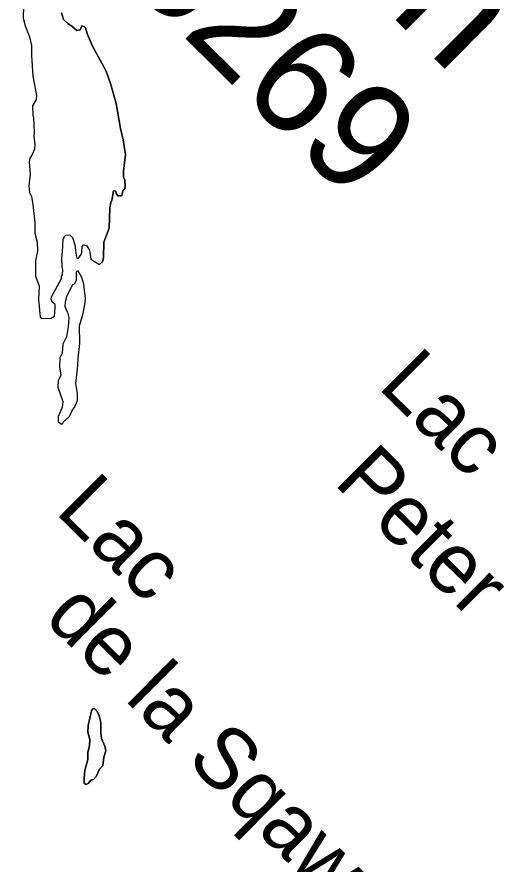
# Model space of a CAD drawing. Extents: x 642515 to 647219, y 6080136 to 6084356.
# Drawn here: x 645090.28 to 645112.82, y 6080946.67 to 6080985.89 of the extents above; entities that cross this region are included whole.
import ezdxf

# ---------------------------------------------------------------- set-up
doc = ezdxf.new("R2010")
doc.units = 0
doc.layers.add('Level 63', color=7, linetype='Continuous')

msp = doc.modelspace()

# ---------------------------------------------------------------- linework, layer by layer
at = {"layer": 'Level 63'}
for points in [[(645090.58, 6080986.39), (645090.56, 6080985.84), (645090.65, 6080985.48), (645090.85, 6080984.97), (645090.95, 6080984.57), (645090.95, 6080984.09), (645091.01, 6080983.16), (645091.18, 6080982.25), (645091.16, 6080982.07), (645090.99, 6080981.78), (645091.01, 6080981.35), (645091.04, 6080981.24), (645091.07, 6080980.56), (645091.05, 6080980.35), (645091.11, 6080979.99), (645091.09, 6080979.78), (645090.98, 6080979.52), (645090.87, 6080979.36), (645090.84, 6080979.19), (645090.89, 6080978.61), (645090.83, 6080978.07), (645090.85, 6080977.77), (645090.95, 6080977.58), (645091.01, 6080977.21), (645091.1, 6080976.38), (645091.1, 6080975.89), (645091.21, 6080975.47), (645091.22, 6080975.06), (645091.13, 6080974.6), (645091.14, 6080973.9), (645091.3, 6080973.44), (645091.27, 6080972.81), (645091.35, 6080971.99), (645091.44, 6080971.93), (645091.86, 6080971.95), (645092.01, 6080972.04), (645092.05, 6080972.41), (645092.04, 6080972.58), (645091.91, 6080972.69), (645091.86, 6080972.82), (645091.88, 6080972.93), (645092.34, 6080973.78), (645092.34, 6080973.86), (645092.38, 6080973.97), (645092.4, 6080974.2), (645092.36, 6080974.33), (645092.35, 6080974.71), (645092.39, 6080975.04), (645092.41, 6080975.59), (645092.47, 6080975.73), (645092.54, 6080975.79), (645092.72, 6080975.81), (645092.85, 6080975.68), (645092.96, 6080975.34), (645093.01, 6080974.85), (645093.04, 6080974.73), (645093.12, 6080974.73), (645093.24, 6080974.9), (645093.28, 6080974.99), (645093.3, 6080975.26), (645093.36, 6080975.34), (645093.5, 6080975.31), (645093.64, 6080975.1), (645093.69, 6080974.68), (645094.09, 6080974.44)], [(645090.58, 6080986.39), (645090.56, 6080985.84), (645090.65, 6080985.48), (645090.85, 6080984.97), (645090.95, 6080984.57), (645090.95, 6080984.09), (645091.01, 6080983.16), (645091.18, 6080982.25), (645091.16, 6080982.07), (645090.99, 6080981.78), (645091.01, 6080981.35), (645091.04, 6080981.24), (645091.07, 6080980.56), (645091.05, 6080980.35), (645091.11, 6080979.99), (645091.09, 6080979.78), (645090.98, 6080979.52), (645090.87, 6080979.36), (645090.84, 6080979.19), (645090.89, 6080978.61), (645090.83, 6080978.07), (645090.85, 6080977.77), (645090.95, 6080977.58), (645091.01, 6080977.21), (645091.1, 6080976.38), (645091.1, 6080975.89), (645091.21, 6080975.47), (645091.22, 6080975.06), (645091.13, 6080974.6), (645091.14, 6080973.9)], [(645092.33, 6080986.09), (645092.43, 6080985.77), (645092.64, 6080985.57), (645092.82, 6080985.47), (645093.05, 6080985.27), (645093.2, 6080985.3), (645093.28, 6080985.48), (645093.38, 6080985.46), (645093.44, 6080985.39), (645093.54, 6080985.08), (645093.77, 6080984.54), (645094.41, 6080983.38), (645094.61, 6080982.81), (645094.87, 6080981.89), (645095.07, 6080980.73), (645095.19, 6080980.2), (645095.3, 6080979.53), (645095.2, 6080978.76)], [(645094.09, 6080974.44), (645094.24, 6080974.55), (645094.28, 6080974.75), (645094.3, 6080975.47), (645094.54, 6080976.12), (645094.58, 6080977.06), (645094.62, 6080977.31), (645094.67, 6080977.39), (645094.75, 6080977.84), (645094.85, 6080977.83), (645094.87, 6080977.72), (645094.95, 6080977.61), (645095.13, 6080977.61), (645095.18, 6080977.84), (645095.26, 6080977.94), (645095.28, 6080978.04), (645095.27, 6080978.34), (645095.21, 6080978.48), (645095.2, 6080978.76), (645095.3, 6080979.53), (645095.19, 6080980.2), (645095.07, 6080980.73), (645094.87, 6080981.89), (645094.61, 6080982.81), (645094.41, 6080983.38), (645093.77, 6080984.54), (645093.54, 6080985.08), (645093.44, 6080985.39), (645093.38, 6080985.46), (645093.28, 6080985.48), (645093.2, 6080985.3), (645093.05, 6080985.27), (645092.82, 6080985.47), (645092.64, 6080985.57), (645092.43, 6080985.77), (645092.33, 6080986.09)], [(645095.2, 6080978.76), (645095.21, 6080978.48), (645095.27, 6080978.34), (645095.28, 6080978.04), (645095.26, 6080977.94), (645095.18, 6080977.84), (645095.13, 6080977.61)], [(645095.13, 6080977.61), (645094.95, 6080977.61), (645094.87, 6080977.72), (645094.85, 6080977.83), (645094.75, 6080977.84), (645094.67, 6080977.39), (645094.62, 6080977.31), (645094.58, 6080977.06), (645094.54, 6080976.12), (645094.3, 6080975.47), (645094.28, 6080974.75), (645094.24, 6080974.55), (645094.09, 6080974.44)], [(645091.14, 6080973.9), (645091.3, 6080973.44), (645091.27, 6080972.81), (645091.35, 6080971.99), (645091.44, 6080971.93), (645091.86, 6080971.95), (645092.01, 6080972.04), (645092.05, 6080972.41), (645092.04, 6080972.58), (645091.91, 6080972.69), (645091.86, 6080972.82), (645091.88, 6080972.93), (645092.34, 6080973.78), (645092.34, 6080973.86), (645092.38, 6080973.97), (645092.4, 6080974.2), (645092.36, 6080974.33), (645092.35, 6080974.71), (645092.39, 6080975.04), (645092.41, 6080975.59), (645092.47, 6080975.73), (645092.54, 6080975.79), (645092.72, 6080975.81), (645092.85, 6080975.68), (645092.96, 6080975.34), (645093.01, 6080974.85), (645093.04, 6080974.73), (645093.12, 6080974.73), (645093.24, 6080974.9), (645093.28, 6080974.99), (645093.3, 6080975.26), (645093.36, 6080975.34), (645093.5, 6080975.31), (645093.64, 6080975.1), (645093.69, 6080974.68), (645094.09, 6080974.44)], [(645093.11, 6080974.14), (645093.01, 6080974.07), (645093.02, 6080973.69), (645092.93, 6080973.52), (645092.84, 6080973.49), (645092.78, 6080973.39), (645092.56, 6080972.91), (645092.5, 6080972.67), (645092.49, 6080972.51), (645092.55, 6080972.33), (645092.62, 6080972.23), (645092.67, 6080971.98), (645092.65, 6080971.55), (645092.57, 6080971.08), (645092.4, 6080970.74), (645092.37, 6080970.32), (645092.26, 6080970.11), (645092.24, 6080969.7), (645092.31, 6080969.31), (645092.18, 6080969.04), (645092.17, 6080968.76), (645092.4, 6080968.09), (645092.37, 6080967.81), (645092.18, 6080967.4), (645092.19, 6080967.16), (645092.31, 6080967.06), (645092.39, 6080967.06), (645092.42, 6080967.14), (645092.7, 6080967.4), (645092.85, 6080967.71), (645092.94, 6080967.81), (645093.08, 6080968.13), (645093.07, 6080968.46), (645093, 6080968.93), (645093.1, 6080969.74), (645093.11, 6080970.09), (645093.19, 6080970.77), (645093.17, 6080971.6), (645093.34, 6080972.16), (645093.42, 6080972.58), (645093.44, 6080972.84), (645093.37, 6080973.52), (645093.28, 6080973.83), (645093.11, 6080974.14)], [(645093.28, 6080973.83), (645093.11, 6080974.14), (645093.01, 6080974.07), (645093.02, 6080973.69), (645092.93, 6080973.52), (645092.84, 6080973.49), (645092.78, 6080973.39), (645092.56, 6080972.91), (645092.5, 6080972.67), (645092.49, 6080972.51), (645092.55, 6080972.33), (645092.62, 6080972.23), (645092.67, 6080971.98), (645092.65, 6080971.55), (645092.57, 6080971.08), (645092.4, 6080970.74), (645092.37, 6080970.32), (645092.26, 6080970.11), (645092.24, 6080969.7), (645092.31, 6080969.31), (645092.18, 6080969.04), (645092.17, 6080968.76), (645092.4, 6080968.09), (645092.37, 6080967.81), (645092.18, 6080967.4), (645092.19, 6080967.16), (645092.31, 6080967.06), (645092.39, 6080967.06), (645092.42, 6080967.14), (645092.7, 6080967.4), (645092.85, 6080967.71), (645092.94, 6080967.81), (645093.08, 6080968.13), (645093.07, 6080968.46), (645093, 6080968.93), (645093.1, 6080969.74), (645093.11, 6080970.09), (645093.19, 6080970.77), (645093.17, 6080971.6), (645093.34, 6080972.16), (645093.42, 6080972.58), (645093.44, 6080972.84), (645093.37, 6080973.52), (645093.28, 6080973.83)], [(645093.55, 6080951.85), (645093.63, 6080952.15), (645093.65, 6080952.44), (645093.56, 6080952.78), (645093.57, 6080953.09), (645093.72, 6080953.77), (645093.79, 6080953.86), (645093.87, 6080953.87), (645093.98, 6080953.74), (645094.08, 6080953.53), (645094.16, 6080953.22), (645094.15, 6080952.77), (645094.19, 6080952.48), (645094.34, 6080952.13), (645094.39, 6080951.91), (645094.29, 6080951.62), (645094.25, 6080951.24), (645094.09, 6080951.06), (645093.94, 6080950.72), (645093.82, 6080950.58), (645093.69, 6080950.55), (645093.57, 6080950.4), (645093.47, 6080950.35), (645093.39, 6080950.41), (645093.38, 6080950.65), (645093.41, 6080951), (645093.56, 6080951.51), (645093.55, 6080951.85)], [(645093.55, 6080951.85), (645093.56, 6080951.51), (645093.41, 6080951), (645093.38, 6080950.65), (645093.39, 6080950.41), (645093.47, 6080950.35), (645093.57, 6080950.4), (645093.69, 6080950.55), (645093.82, 6080950.58), (645093.94, 6080950.72), (645094.09, 6080951.06), (645094.25, 6080951.24), (645094.29, 6080951.62), (645094.39, 6080951.91), (645094.34, 6080952.13), (645094.19, 6080952.48), (645094.15, 6080952.77), (645094.16, 6080953.22), (645094.08, 6080953.53), (645093.98, 6080953.74), (645093.87, 6080953.87), (645093.79, 6080953.86), (645093.72, 6080953.77), (645093.57, 6080953.09), (645093.56, 6080952.78), (645093.65, 6080952.44), (645093.63, 6080952.15), (645093.55, 6080951.85)]]:
    msp.add_lwpolyline(points, dxfattribs=at)

# ---------------------------------------------------------------- texts
for s, height, rotation, p in [('Kawawachikamach', 5.66682, 315.1735, (645064.41, 6081028.87)), ('5269', 5, 315.1735, (645095.2, 6080987.75)), ('Lac', 2.8334, 315.1735, (645106.93, 6080968.75)), ('National topographic sheet  23/J15', 5.66682, 315.1752, (645021.23, 6080964.23)), ('Peter', 2.8334, 315.1735, (645104.89, 6080964.3)), ('Lac ', 2.8334, 315.1735, (645092, 6080962.96)), ('de la Sqaw', 2.8334, 315.1735, (645091.48, 6080958))]:
    msp.add_text(s, height=height, rotation=rotation, dxfattribs=at).set_placement(p)

doc.saveas('drawing.dxf')
